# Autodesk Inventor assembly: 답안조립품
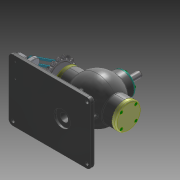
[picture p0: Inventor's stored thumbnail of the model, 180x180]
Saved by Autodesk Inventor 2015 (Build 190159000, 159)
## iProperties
Created: 2017-07
Part Number: 답안조립품
Document SubType Name: Assembly
Designer: owner
Mass: 3277.38 g
Surface Area: 2432.27 cm^2
Volume: 944.503 cm^3
Density: 3.46995 g/cm^3
Author: owner
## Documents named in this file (20)
- C:\Users\owner\Desktop\370707V1012\답안조립품.iam
- C:\Users\owner\Desktop\370707V1012\본체.ipt
- C:\Users\owner\Desktop\370707V1012\축.ipt
- C:\Users\owner\Desktop\370707V1012\키 3 x 3 x 12.ipt
- C:\Users\owner\Desktop\370707V1012\베어링 6202.ipt
- C:\Users\owner\Desktop\370707V1012\뒤커버.ipt
- C:\Users\owner\Desktop\370707V1012\볼트 M4x12.ipt
- C:\Users\owner\Desktop\370707V1012\앞커버.ipt
- C:\Users\owner\Desktop\370707V1012\오일실.ipt
- C:\Users\owner\Desktop\370707V1012\스프로킷.ipt
- C:\Users\owner\Desktop\370707V1012\너트 M8x1.ipt
- C:\Users\owner\Desktop\370707V1012\와셔 8x17.ipt
- C:\Users\owner\Desktop\370707V1012\고정핀.ipt
- C:\Users\owner\Desktop\370707V1012\연결대.ipt
- C:\Users\owner\Desktop\370707V1012\둥근머리 볼트 M4x8.ipt
- C:\Users\owner\Desktop\370707V1012\와셔 ISO 7093 A.ipt
- C:\Users\owner\Desktop\370707V1012\본체커버.ipt
- C:\Users\owner\Desktop\370707V1012\슬라이드 커버.ipt
- C:\Users\owner\Desktop\370707V1012\슬라이드.ipt
- C:\Users\owner\Desktop\370707V1012\스프링.ipt
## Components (1 placed, 1 different names)
1. 고정핀:1
